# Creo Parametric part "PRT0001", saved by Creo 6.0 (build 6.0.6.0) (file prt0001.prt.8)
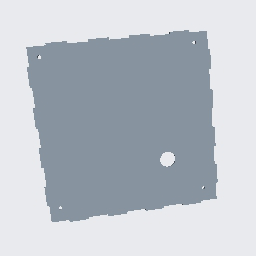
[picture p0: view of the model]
Units: Inch lbm Second (Pro/E Default); INCH, POUND, SECS

Created from: INLBS_PART_SOLID.PRT

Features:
  1. datum plane "RIGHT"
  2. datum plane "TOP"
  3. datum plane "FRONT"
  4. coordinate system
  5. sketch "Sketch 1"
  6. extrusion "Extrude 1"
  7. sketch "Sketch 2"
  8. extruded cut "Extrude 2"
  9. sketch "Sketch 3"
  10. extruded cut "Extrude 3"
  11. sketch "Sketch 4"
  12. extruded cut "Extrude 4"

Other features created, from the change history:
  extrusion "Extrude 2" (2 times)
  mirror "Mirror 1"

Surfaces: 70 plane, 5 cylinder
